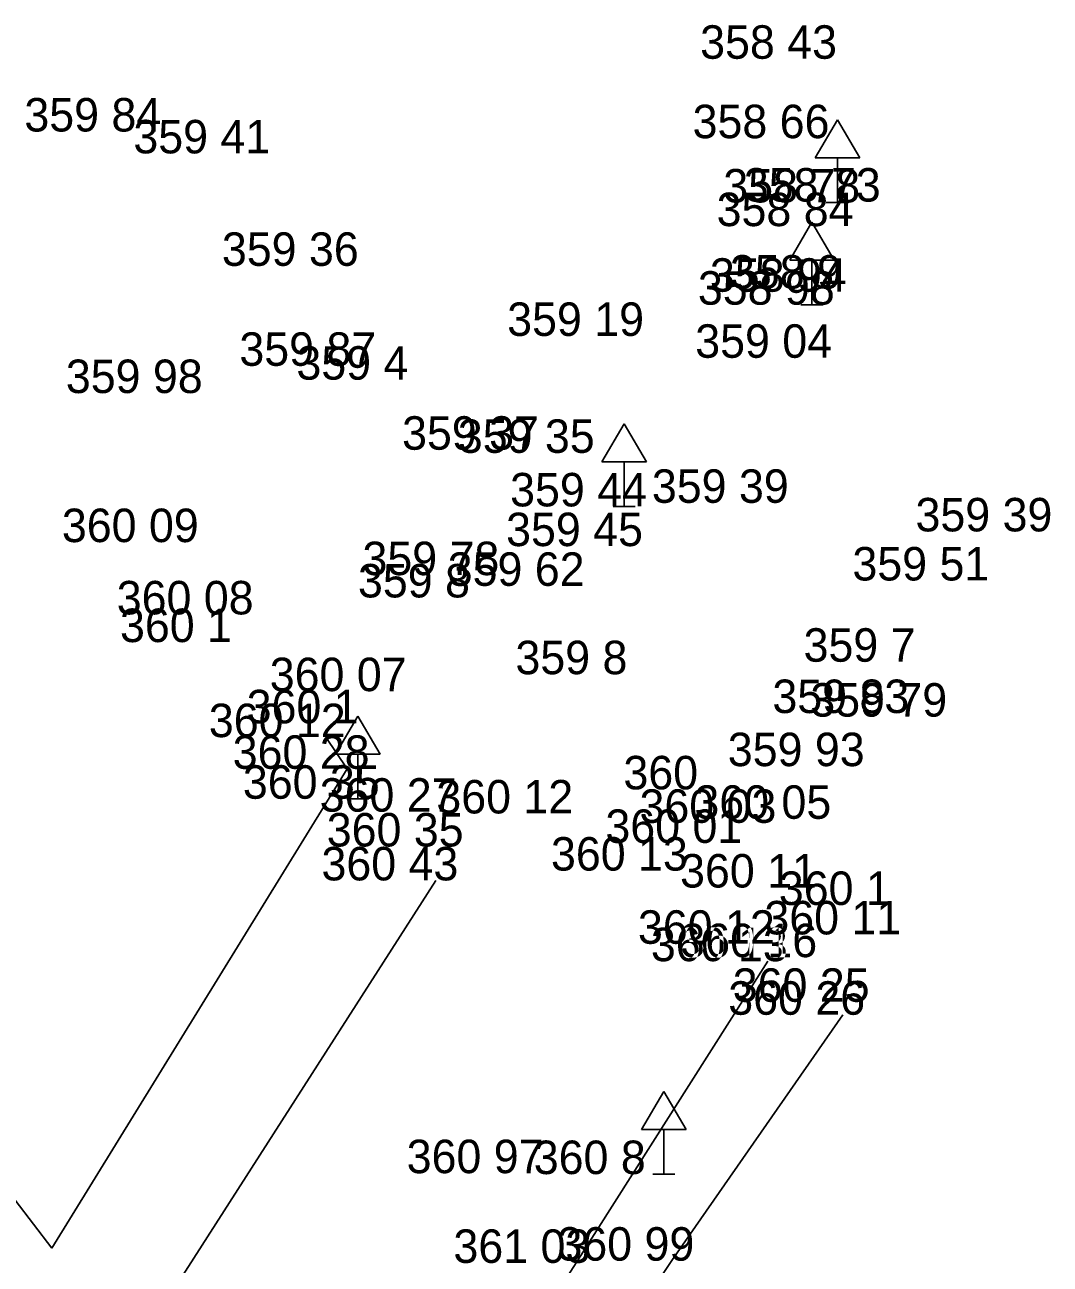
# Model space of a CAD drawing. Extents: x -688316 to -688024, y -973785 to -973591.
# Drawn here: x -688068.85 to -688045.86, y -973630.22 to -973602.45 of the extents above; entities that cross this region are included whole.
import ezdxf

# ---------------------------------------------------------------- set-up
doc = ezdxf.new("R2010")
doc.units = 0
for name, color, linetype in [('Vrstva 10', 7, 'Continuous'), ('Vrstva 3', 7, 'Continuous'), ('Vrstva 34', 7, 'Continuous'), ('Vrstva 5', 7, 'Continuous'), ('Vrstva 6', 7, 'Continuous')]:
    doc.layers.add(name, color=color, linetype=linetype)

# ---------------------------------------------------------------- blocks, each defined once
blk = doc.blocks.new('DZ')
at = {"layer": 'Vrstva 34'}
for p, q in [((-5, 10), (0, 18.5)), ((0, 18.5), (5, 10)), ((-5, 10), (5, 10)), ((0, 0), (0, 10)), ((-2.49, 0), (2.49, 0))]:
    blk.add_line(p, q, dxfattribs=at)

msp = doc.modelspace()

# ---------------------------------------------------------------- linework, layer by layer
at = {"layer": 'Vrstva 10'}
for p, q in [((-688066.34, -973632.08), (-688059.63, -973621.62)), ((-688056.49, -973630.19), (-688052.19, -973623.43)), ((-688061.38, -973637.79), (-688056.49, -973630.19))]:
    msp.add_line(p, q, dxfattribs=at)
at = {"layer": 'Vrstva 5'}
for p, q in [((-688068.24, -973629.86), (-688072.13, -973624.79)), ((-688054.34, -973630.14), (-688050.51, -973624.63))]:
    msp.add_line(p, q, dxfattribs=at)
msp.add_lwpolyline([(-688062.1, -973618.41), (-688061.62, -973619.12), (-688068.24, -973629.86)], dxfattribs=at)
at = {"layer": 'Vrstva 6'}
msp.add_line((-688054.34, -973630.14), (-688054.92, -973631), dxfattribs=at)

# ---------------------------------------------------------------- block references
at = {"layer": 'Vrstva 34', "xscale": 0.1, "yscale": 0.10000000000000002}
for p in [(-688050.63, -973606.43), (-688050.63, -973606.43), (-688050.63, -973606.43), (-688050.63, -973606.43), (-688051.2, -973608.72), (-688051.2, -973608.72), (-688051.2, -973608.72), (-688051.2, -973608.72), (-688055.41, -973613.24), (-688055.41, -973613.24), (-688055.41, -973613.24), (-688055.41, -973613.24), (-688061.38, -973619.79), (-688061.38, -973619.79), (-688061.38, -973619.79), (-688061.38, -973619.79), (-688054.52, -973628.2), (-688054.52, -973628.2), (-688054.52, -973628.2), (-688054.52, -973628.2)]:
    msp.add_blockref('DZ', p, dxfattribs=at)

# ---------------------------------------------------------------- texts
at = {"layer": 'Vrstva 3'}
for s, p in [('358 43 ', (-688053.707, -973603.21)), ('358 43 ', (-688053.707, -973603.21)), ('358 43 ', (-688053.707, -973603.21)), ('358 43 ', (-688053.707, -973603.21)), ('358 43 ', (-688053.707, -973603.21)), ('358 43 ', (-688053.707, -973603.21)), ('358 43 ', (-688053.707, -973603.21)), ('359 84 ', (-688068.857, -973604.84)), ('359 84 ', (-688068.857, -973604.84)), ('359 84 ', (-688068.857, -973604.84)), ('359 84 ', (-688068.857, -973604.84)), ('359 84 ', (-688068.857, -973604.84)), ('359 84 ', (-688068.857, -973604.84)), ('359 84 ', (-688068.857, -973604.84)), ('358 66 ', (-688053.876, -973604.99)), ('358 66 ', (-688053.876, -973604.99)), ('358 66 ', (-688053.876, -973604.99)), ('358 66 ', (-688053.876, -973604.99)), ('358 66 ', (-688053.876, -973604.99)), ('358 66 ', (-688053.876, -973604.99)), ('358 66 ', (-688053.876, -973604.99)), ('359 41 ', (-688066.413, -973605.33)), ('359 41 ', (-688066.413, -973605.33)), ('359 41 ', (-688066.413, -973605.33)), ('359 41 ', (-688066.413, -973605.33)), ('359 41 ', (-688066.413, -973605.33)), ('359 41 ', (-688066.413, -973605.33)), ('359 41 ', (-688066.413, -973605.33)), ('358 78 ', (-688053.187, -973606.43)), ('358 78 ', (-688053.187, -973606.43)), ('358 78 ', (-688053.187, -973606.43)), ('358 78 ', (-688053.187, -973606.43)), ('358 78 ', (-688053.187, -973606.43)), ('358 78 ', (-688053.187, -973606.43)), ('358 78 ', (-688053.187, -973606.43)), ('358 73 ', (-688052.727, -973606.41)), ('358 73 ', (-688052.727, -973606.41)), ('358 73 ', (-688052.727, -973606.41)), ('358 73 ', (-688052.727, -973606.41)), ('358 73 ', (-688052.727, -973606.41)), ('358 73 ', (-688052.727, -973606.41)), ('358 73 ', (-688052.727, -973606.41)), ('358 84 ', (-688053.337, -973606.96)), ('358 84 ', (-688053.337, -973606.96)), ('358 84 ', (-688053.337, -973606.96)), ('358 84 ', (-688053.337, -973606.96)), ('358 84 ', (-688053.337, -973606.96)), ('358 84 ', (-688053.337, -973606.96)), ('358 84 ', (-688053.337, -973606.96)), ('359 36 ', (-688064.429, -973607.85)), ('359 36 ', (-688064.429, -973607.85)), ('359 36 ', (-688064.429, -973607.85)), ('359 36 ', (-688064.429, -973607.85)), ('359 36 ', (-688064.429, -973607.85)), ('359 36 ', (-688064.429, -973607.85)), ('359 36 ', (-688064.429, -973607.85)), ('358 9  ', (-688053.038, -973608.36)), ('358 9  ', (-688053.038, -973608.36)), ('358 9  ', (-688053.038, -973608.36)), ('358 9  ', (-688053.038, -973608.36)), ('358 9  ', (-688053.038, -973608.36)), ('358 9  ', (-688053.038, -973608.36)), ('358 9  ', (-688053.038, -973608.36)), ('358 94 ', (-688053.487, -973608.43)), ('358 94 ', (-688053.487, -973608.43)), ('358 94 ', (-688053.487, -973608.43)), ('358 94 ', (-688053.487, -973608.43)), ('358 94 ', (-688053.487, -973608.43)), ('358 94 ', (-688053.487, -973608.43)), ('358 94 ', (-688053.487, -973608.43)), ('358 98 ', (-688053.757, -973608.72)), ('358 98 ', (-688053.757, -973608.72)), ('358 98 ', (-688053.757, -973608.72)), ('358 98 ', (-688053.757, -973608.72)), ('358 98 ', (-688053.757, -973608.72)), ('358 98 ', (-688053.757, -973608.72)), ('358 98 ', (-688053.757, -973608.72)), ('359 19 ', (-688058.033, -973609.42)), ('359 19 ', (-688058.033, -973609.42)), ('359 19 ', (-688058.033, -973609.42)), ('359 19 ', (-688058.033, -973609.42)), ('359 19 ', (-688058.033, -973609.42)), ('359 19 ', (-688058.033, -973609.42)), ('359 19 ', (-688058.033, -973609.42)), ('359 04 ', (-688053.817, -973609.91)), ('359 04 ', (-688053.817, -973609.91)), ('359 04 ', (-688053.817, -973609.91)), ('359 04 ', (-688053.817, -973609.91)), ('359 04 ', (-688053.817, -973609.91)), ('359 04 ', (-688053.817, -973609.91)), ('359 04 ', (-688053.817, -973609.91)), ('359 87 ', (-688064.037, -973610.09)), ('359 87 ', (-688064.037, -973610.09)), ('359 87 ', (-688064.037, -973610.09)), ('359 87 ', (-688064.037, -973610.09)), ('359 87 ', (-688064.037, -973610.09)), ('359 87 ', (-688064.037, -973610.09)), ('359 87 ', (-688064.037, -973610.09)), ('359 4  ', (-688062.758, -973610.4)), ('359 4  ', (-688062.758, -973610.4)), ('359 4  ', (-688062.758, -973610.4)), ('359 4  ', (-688062.758, -973610.4)), ('359 4  ', (-688062.758, -973610.4)), ('359 4  ', (-688062.758, -973610.4)), ('359 4  ', (-688062.758, -973610.4)), ('359 98 ', (-688067.927, -973610.7)), ('359 98 ', (-688067.927, -973610.7)), ('359 98 ', (-688067.927, -973610.7)), ('359 98 ', (-688067.927, -973610.7)), ('359 98 ', (-688067.927, -973610.7)), ('359 98 ', (-688067.927, -973610.7)), ('359 98 ', (-688067.927, -973610.7)), ('359 37 ', (-688060.389, -973611.97)), ('359 37 ', (-688060.389, -973611.97)), ('359 37 ', (-688060.389, -973611.97)), ('359 37 ', (-688060.389, -973611.97)), ('359 37 ', (-688060.389, -973611.97)), ('359 37 ', (-688060.389, -973611.97)), ('359 37 ', (-688060.389, -973611.97)), ('359 35 ', (-688059.139, -973612.04)), ('359 35 ', (-688059.139, -973612.04)), ('359 35 ', (-688059.139, -973612.04)), ('359 35 ', (-688059.139, -973612.04)), ('359 35 ', (-688059.139, -973612.04)), ('359 35 ', (-688059.139, -973612.04)), ('359 35 ', (-688059.139, -973612.04)), ('359 44 ', (-688057.967, -973613.24)), ('359 44 ', (-688057.967, -973613.24)), ('359 44 ', (-688057.967, -973613.24)), ('359 44 ', (-688057.967, -973613.24)), ('359 44 ', (-688057.967, -973613.24)), ('359 44 ', (-688057.967, -973613.24)), ('359 44 ', (-688057.967, -973613.24)), ('359 39 ', (-688054.789, -973613.16)), ('359 39 ', (-688054.789, -973613.16)), ('359 39 ', (-688054.789, -973613.16)), ('359 39 ', (-688054.789, -973613.16)), ('359 39 ', (-688054.789, -973613.16)), ('359 39 ', (-688054.789, -973613.16)), ('359 39 ', (-688054.789, -973613.16)), ('359 39 ', (-688048.879, -973613.8)), ('359 39 ', (-688048.879, -973613.8)), ('359 39 ', (-688048.879, -973613.8)), ('359 39 ', (-688048.879, -973613.8)), ('359 39 ', (-688048.879, -973613.8)), ('359 39 ', (-688048.879, -973613.8)), ('359 39 ', (-688048.879, -973613.8)), ('360 09 ', (-688068.016, -973614.04)), ('360 09 ', (-688068.016, -973614.04)), ('360 09 ', (-688068.016, -973614.04)), ('360 09 ', (-688068.016, -973614.04)), ('360 09 ', (-688068.016, -973614.04)), ('360 09 ', (-688068.016, -973614.04)), ('360 09 ', (-688068.016, -973614.04)), ('359 45 ', (-688058.057, -973614.13)), ('359 45 ', (-688058.057, -973614.13)), ('359 45 ', (-688058.057, -973614.13)), ('359 45 ', (-688058.057, -973614.13)), ('359 45 ', (-688058.057, -973614.13)), ('359 45 ', (-688058.057, -973614.13)), ('359 45 ', (-688058.057, -973614.13)), ('359 78 ', (-688061.277, -973614.78)), ('359 78 ', (-688061.277, -973614.78)), ('359 78 ', (-688061.277, -973614.78)), ('359 78 ', (-688061.277, -973614.78)), ('359 78 ', (-688061.277, -973614.78)), ('359 78 ', (-688061.277, -973614.78)), ('359 78 ', (-688061.277, -973614.78)), ('359 62 ', (-688059.366, -973615.02)), ('359 62 ', (-688059.366, -973615.02)), ('359 62 ', (-688059.366, -973615.02)), ('359 62 ', (-688059.366, -973615.02)), ('359 62 ', (-688059.366, -973615.02)), ('359 62 ', (-688059.366, -973615.02)), ('359 62 ', (-688059.366, -973615.02)), ('359 51 ', (-688050.293, -973614.9)), ('359 51 ', (-688050.293, -973614.9)), ('359 51 ', (-688050.293, -973614.9)), ('359 51 ', (-688050.293, -973614.9)), ('359 51 ', (-688050.293, -973614.9)), ('359 51 ', (-688050.293, -973614.9)), ('359 51 ', (-688050.293, -973614.9)), ('359 8  ', (-688061.378, -973615.28)), ('359 8  ', (-688061.378, -973615.28)), ('359 8  ', (-688061.378, -973615.28)), ('359 8  ', (-688061.378, -973615.28)), ('359 8  ', (-688061.378, -973615.28)), ('359 8  ', (-688061.378, -973615.28)), ('359 8  ', (-688061.378, -973615.28)), ('360 08 ', (-688066.786, -973615.66)), ('360 08 ', (-688066.786, -973615.66)), ('360 08 ', (-688066.786, -973615.66)), ('360 08 ', (-688066.786, -973615.66)), ('360 08 ', (-688066.786, -973615.66)), ('360 08 ', (-688066.786, -973615.66)), ('360 08 ', (-688066.786, -973615.66)), ('360 1  ', (-688066.713, -973616.28)), ('360 1  ', (-688066.713, -973616.28)), ('360 1  ', (-688066.713, -973616.28)), ('360 1  ', (-688066.713, -973616.28)), ('360 1  ', (-688066.713, -973616.28)), ('360 1  ', (-688066.713, -973616.28)), ('360 1  ', (-688066.713, -973616.28)), ('359 7  ', (-688051.388, -973616.72)), ('359 7  ', (-688051.388, -973616.72)), ('359 7  ', (-688051.388, -973616.72)), ('359 7  ', (-688051.388, -973616.72)), ('359 7  ', (-688051.388, -973616.72)), ('359 7  ', (-688051.388, -973616.72)), ('359 7  ', (-688051.388, -973616.72)), ('359 8  ', (-688057.848, -973617)), ('359 8  ', (-688057.848, -973617)), ('359 8  ', (-688057.848, -973617)), ('359 8  ', (-688057.848, -973617)), ('359 8  ', (-688057.848, -973617)), ('359 8  ', (-688057.848, -973617)), ('359 8  ', (-688057.848, -973617)), ('360 07 ', (-688063.356, -973617.38)), ('360 07 ', (-688063.356, -973617.38)), ('360 07 ', (-688063.356, -973617.38)), ('360 07 ', (-688063.356, -973617.38)), ('360 07 ', (-688063.356, -973617.38)), ('360 07 ', (-688063.356, -973617.38)), ('360 07 ', (-688063.356, -973617.38)), ('360 1  ', (-688063.873, -973618.1)), ('360 1  ', (-688063.873, -973618.1)), ('360 1  ', (-688063.873, -973618.1)), ('360 1  ', (-688063.873, -973618.1)), ('360 1  ', (-688063.873, -973618.1)), ('360 1  ', (-688063.873, -973618.1)), ('360 1  ', (-688063.873, -973618.1)), ('359 83 ', (-688052.087, -973617.87)), ('359 83 ', (-688052.087, -973617.87)), ('359 83 ', (-688052.087, -973617.87)), ('359 83 ', (-688052.087, -973617.87)), ('359 83 ', (-688052.087, -973617.87)), ('359 83 ', (-688052.087, -973617.87)), ('359 83 ', (-688052.087, -973617.87)), ('359 79 ', (-688051.237, -973617.95)), ('359 79 ', (-688051.237, -973617.95)), ('359 79 ', (-688051.237, -973617.95)), ('359 79 ', (-688051.237, -973617.95)), ('359 79 ', (-688051.237, -973617.95)), ('359 79 ', (-688051.237, -973617.95)), ('359 79 ', (-688051.237, -973617.95)), ('360 12 ', (-688064.721, -973618.41)), ('360 12 ', (-688064.721, -973618.41)), ('360 12 ', (-688064.721, -973618.41)), ('360 12 ', (-688064.721, -973618.41)), ('360 12 ', (-688064.721, -973618.41)), ('360 12 ', (-688064.721, -973618.41)), ('360 12 ', (-688064.721, -973618.41)), ('360 28 ', (-688064.186, -973619.12)), ('360 28 ', (-688064.186, -973619.12)), ('360 28 ', (-688064.186, -973619.12)), ('360 28 ', (-688064.186, -973619.12)), ('360 28 ', (-688064.186, -973619.12)), ('360 28 ', (-688064.186, -973619.12)), ('360 28 ', (-688064.186, -973619.12)), ('359 93 ', (-688053.087, -973619.06)), ('359 93 ', (-688053.087, -973619.06)), ('359 93 ', (-688053.087, -973619.06)), ('359 93 ', (-688053.087, -973619.06)), ('359 93 ', (-688053.087, -973619.06)), ('359 93 ', (-688053.087, -973619.06)), ('359 93 ', (-688053.087, -973619.06)), ('360    ', (-688055.427, -973619.58)), ('360    ', (-688055.427, -973619.58)), ('360    ', (-688055.427, -973619.58)), ('360    ', (-688055.427, -973619.58)), ('360    ', (-688055.427, -973619.58)), ('360    ', (-688055.427, -973619.58)), ('360    ', (-688055.427, -973619.58)), ('360 35 ', (-688063.958, -973619.79)), ('360 35 ', (-688063.958, -973619.79)), ('360 35 ', (-688063.958, -973619.79)), ('360 35 ', (-688063.958, -973619.79)), ('360 35 ', (-688063.958, -973619.79)), ('360 35 ', (-688063.958, -973619.79)), ('360 35 ', (-688063.958, -973619.79)), ('360 27 ', (-688062.236, -973620.08)), ('360 27 ', (-688062.236, -973620.08)), ('360 27 ', (-688062.236, -973620.08)), ('360 27 ', (-688062.236, -973620.08)), ('360 27 ', (-688062.236, -973620.08)), ('360 27 ', (-688062.236, -973620.08)), ('360 27 ', (-688062.236, -973620.08)), ('360 12 ', (-688059.621, -973620.12)), ('360 12 ', (-688059.621, -973620.12)), ('360 12 ', (-688059.621, -973620.12)), ('360 12 ', (-688059.621, -973620.12)), ('360 12 ', (-688059.621, -973620.12)), ('360 12 ', (-688059.621, -973620.12)), ('360 12 ', (-688059.621, -973620.12)), ('360 03 ', (-688055.066, -973620.33)), ('360 03 ', (-688055.066, -973620.33)), ('360 03 ', (-688055.066, -973620.33)), ('360 03 ', (-688055.066, -973620.33)), ('360 03 ', (-688055.066, -973620.33)), ('360 03 ', (-688055.066, -973620.33)), ('360 03 ', (-688055.066, -973620.33)), ('360 05 ', (-688053.836, -973620.24)), ('360 05 ', (-688053.836, -973620.24)), ('360 05 ', (-688053.836, -973620.24)), ('360 05 ', (-688053.836, -973620.24)), ('360 05 ', (-688053.836, -973620.24)), ('360 05 ', (-688053.836, -973620.24)), ('360 05 ', (-688053.836, -973620.24)), ('360 35 ', (-688062.078, -973620.86)), ('360 35 ', (-688062.078, -973620.86)), ('360 35 ', (-688062.078, -973620.86)), ('360 35 ', (-688062.078, -973620.86)), ('360 35 ', (-688062.078, -973620.86)), ('360 35 ', (-688062.078, -973620.86)), ('360 35 ', (-688062.078, -973620.86)), ('360 01 ', (-688055.831, -973620.78)), ('360 01 ', (-688055.831, -973620.78)), ('360 01 ', (-688055.831, -973620.78)), ('360 01 ', (-688055.831, -973620.78)), ('360 01 ', (-688055.831, -973620.78)), ('360 01 ', (-688055.831, -973620.78)), ('360 01 ', (-688055.831, -973620.78)), ('360 13 ', (-688057.051, -973621.4)), ('360 13 ', (-688057.051, -973621.4)), ('360 13 ', (-688057.051, -973621.4)), ('360 13 ', (-688057.051, -973621.4)), ('360 13 ', (-688057.051, -973621.4)), ('360 13 ', (-688057.051, -973621.4)), ('360 13 ', (-688057.051, -973621.4)), ('360 43 ', (-688062.196, -973621.62)), ('360 43 ', (-688062.196, -973621.62)), ('360 43 ', (-688062.196, -973621.62)), ('360 43 ', (-688062.196, -973621.62)), ('360 43 ', (-688062.196, -973621.62)), ('360 43 ', (-688062.196, -973621.62)), ('360 43 ', (-688062.196, -973621.62)), ('360 11 ', (-688054.157, -973621.78)), ('360 11 ', (-688054.157, -973621.78)), ('360 11 ', (-688054.157, -973621.78)), ('360 11 ', (-688054.157, -973621.78)), ('360 11 ', (-688054.157, -973621.78)), ('360 11 ', (-688054.157, -973621.78)), ('360 11 ', (-688054.157, -973621.78)), ('360 1  ', (-688051.943, -973622.17)), ('360 1  ', (-688051.943, -973622.17)), ('360 1  ', (-688051.943, -973622.17)), ('360 1  ', (-688051.943, -973622.17)), ('360 1  ', (-688051.943, -973622.17)), ('360 1  ', (-688051.943, -973622.17)), ('360 1  ', (-688051.943, -973622.17)), ('360 11 ', (-688052.267, -973622.83)), ('360 11 ', (-688052.267, -973622.83)), ('360 11 ', (-688052.267, -973622.83)), ('360 11 ', (-688052.267, -973622.83)), ('360 11 ', (-688052.267, -973622.83)), ('360 11 ', (-688052.267, -973622.83)), ('360 11 ', (-688052.267, -973622.83)), ('360 12 ', (-688055.101, -973623.04)), ('360 12 ', (-688055.101, -973623.04)), ('360 12 ', (-688055.101, -973623.04)), ('360 12 ', (-688055.101, -973623.04)), ('360 12 ', (-688055.101, -973623.04)), ('360 12 ', (-688055.101, -973623.04)), ('360 12 ', (-688055.101, -973623.04)), ('360 16 ', (-688054.151, -973623.34)), ('360 16 ', (-688054.151, -973623.34)), ('360 16 ', (-688054.151, -973623.34)), ('360 16 ', (-688054.151, -973623.34)), ('360 16 ', (-688054.151, -973623.34)), ('360 16 ', (-688054.151, -973623.34)), ('360 16 ', (-688054.151, -973623.34)), ('360 13 ', (-688054.811, -973623.43)), ('360 13 ', (-688054.811, -973623.43)), ('360 13 ', (-688054.811, -973623.43)), ('360 13 ', (-688054.811, -973623.43)), ('360 13 ', (-688054.811, -973623.43)), ('360 13 ', (-688054.811, -973623.43)), ('360 13 ', (-688054.811, -973623.43)), ('360 25 ', (-688052.976, -973624.34)), ('360 25 ', (-688052.976, -973624.34)), ('360 25 ', (-688052.976, -973624.34)), ('360 25 ', (-688052.976, -973624.34)), ('360 25 ', (-688052.976, -973624.34)), ('360 25 ', (-688052.976, -973624.34)), ('360 25 ', (-688052.976, -973624.34)), ('360 26 ', (-688053.076, -973624.63)), ('360 26 ', (-688053.076, -973624.63)), ('360 26 ', (-688053.076, -973624.63)), ('360 26 ', (-688053.076, -973624.63)), ('360 26 ', (-688053.076, -973624.63)), ('360 26 ', (-688053.076, -973624.63)), ('360 26 ', (-688053.076, -973624.63)), ('360 97 ', (-688060.286, -973628.18)), ('360 97 ', (-688060.286, -973628.18)), ('360 97 ', (-688060.286, -973628.18)), ('360 97 ', (-688060.286, -973628.18)), ('360 97 ', (-688060.286, -973628.18)), ('360 97 ', (-688060.286, -973628.18)), ('360 97 ', (-688060.286, -973628.18)), ('360 8  ', (-688057.437, -973628.2)), ('360 8  ', (-688057.437, -973628.2)), ('360 8  ', (-688057.437, -973628.2)), ('360 8  ', (-688057.437, -973628.2)), ('360 8  ', (-688057.437, -973628.2)), ('360 8  ', (-688057.437, -973628.2)), ('360 8  ', (-688057.437, -973628.2)), ('361 03 ', (-688059.238, -973630.19)), ('361 03 ', (-688059.238, -973630.19)), ('361 03 ', (-688059.238, -973630.19)), ('361 03 ', (-688059.238, -973630.19)), ('361 03 ', (-688059.238, -973630.19)), ('361 03 ', (-688059.238, -973630.19)), ('361 03 ', (-688059.238, -973630.19)), ('360 99 ', (-688056.906, -973630.14)), ('360 99 ', (-688056.906, -973630.14)), ('360 99 ', (-688056.906, -973630.14)), ('360 99 ', (-688056.906, -973630.14)), ('360 99 ', (-688056.906, -973630.14)), ('360 99 ', (-688056.906, -973630.14)), ('360 99 ', (-688056.906, -973630.14))]:
    msp.add_text(s, height=0.75, dxfattribs=at).set_placement(p)

doc.saveas('drawing.dxf')
